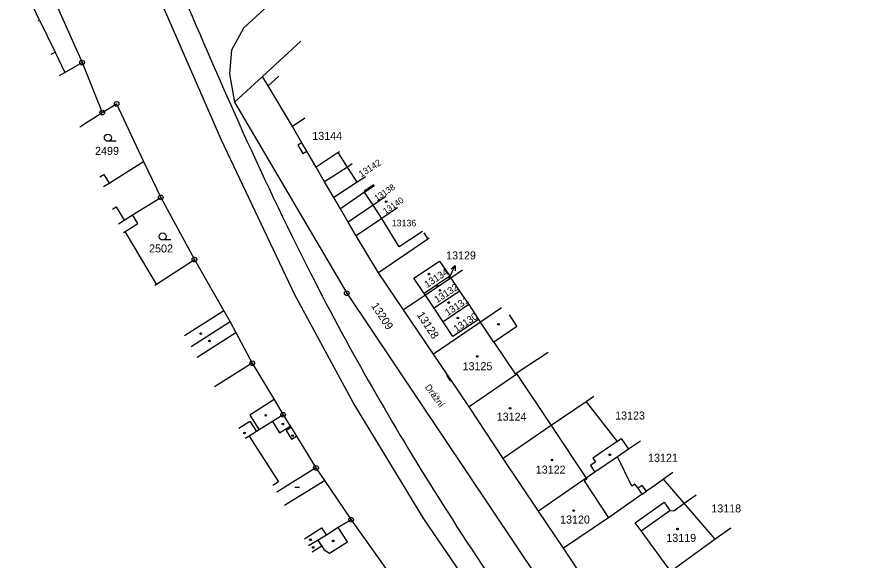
# Model space of a CAD drawing. Extents: x -825057 to -819383, y -1071633 to -1067888.
# Drawn here: x -820683.2 to -820503, y -1071267 to -1071151.6 of the extents above; entities that cross this region are included whole.
import ezdxf

# ---------------------------------------------------------------- set-up
doc = ezdxf.new("R2010")
doc.units = 0
for name, color, linetype in [('Vrstva 1', 7, 'Continuous'), ('Vrstva 10', 7, 'Continuous'), ('Vrstva 15', 7, 'Continuous'), ('Vrstva 16', 7, 'Continuous'), ('Vrstva 18', 7, 'Continuous'), ('Vrstva 19', 7, 'Continuous'), ('Vrstva 24', 7, 'Continuous'), ('Vrstva 25', 7, 'Continuous'), ('Vrstva 4', 7, 'Continuous')]:
    doc.layers.add(name, color=color, linetype=linetype)

msp = doc.modelspace()

# ---------------------------------------------------------------- linework, layer by layer
at = {"layer": 'Vrstva 1'}
for p, q in [((-820603.93, -1071125.41), (-820635.05, -1071153.94)), ((-820683.15, -1071130.16), (-820669.33, -1071161.28)), ((-820678.34, -1071152.24), (-820679.65, -1071149.54)), ((-820678.67, -1071152.4), (-820678.34, -1071152.24)), ((-820678.34, -1071152.24), (-820675.07, -1071159.07)), ((-820635.05, -1071153.94), (-820637.57, -1071158.64)), ((-820630.96, -1071164.21), (-820622.83, -1071156.74)), ((-820675.07, -1071159.07), (-820672.99, -1071163.41)), ((-820637.57, -1071158.64), (-820637.97, -1071163.66)), ((-820672.99, -1071163.41), (-820669.33, -1071161.28)), ((-820669.33, -1071161.28), (-820665.05, -1071171.9)), ((-820674.08, -1071164.01), (-820672.99, -1071163.41)), ((-820637.97, -1071163.66), (-820636.96, -1071169.72)), ((-820636.96, -1071169.72), (-820630.96, -1071164.21)), ((-820629.77, -1071166.21), (-820630.96, -1071164.21)), ((-820624.6, -1071174.87), (-820629.77, -1071166.21)), ((-820665.05, -1071171.9), (-820662, -1071170.07)), ((-820662, -1071170.07), (-820656.29, -1071182.27)), ((-820636.96, -1071169.72), (-820613.1, -1071210.27)), ((-820669.77, -1071174.94), (-820665.05, -1071171.9)), ((-820622.03, -1071173.12), (-820624.6, -1071174.87)), ((-820622.62, -1071178.29), (-820624.6, -1071174.87)), ((-820621.57, -1071180.1), (-820622.62, -1071178.29)), ((-820619.61, -1071183.48), (-820621.57, -1071180.1)), ((-820614.93, -1071180.4), (-820619.61, -1071183.48)), ((-820614.65, -1071180.22), (-820614.93, -1071180.4)), ((-820663.57, -1071186.87), (-820656.29, -1071182.27)), ((-820656.29, -1071182.27), (-820652.59, -1071189.92)), ((-820617.79, -1071186.59), (-820619.61, -1071183.48)), ((-820612.95, -1071183.46), (-820617.79, -1071186.59)), ((-820611.95, -1071182.81), (-820612.95, -1071183.46)), ((-820665.57, -1071185.57), (-820664.7, -1071185.02)), ((-820664.7, -1071185.02), (-820663.57, -1071186.87)), ((-820664.77, -1071187.62), (-820663.57, -1071186.87)), ((-820615.84, -1071189.94), (-820617.79, -1071186.59)), ((-820610.85, -1071186.71), (-820615.84, -1071189.94)), ((-820609.08, -1071185.57), (-820610.85, -1071186.71)), ((-820609.3, -1071188.77), (-820614.45, -1071192.34)), ((-820607.35, -1071187.24), (-820609.41, -1071188.59)), ((-820609.41, -1071188.59), (-820609.3, -1071188.77)), ((-820609.3, -1071188.77), (-820607.22, -1071187.37)), ((-820658.59, -1071193.65), (-820652.59, -1071189.92)), ((-820652.59, -1071189.92), (-820645.44, -1071203.12)), ((-820614.45, -1071192.34), (-820615.84, -1071189.94)), ((-820604.77, -1071189.72), (-820607.49, -1071191.58)), ((-820612.78, -1071195.19), (-820614.45, -1071192.34)), ((-820607.49, -1071191.58), (-820612.78, -1071195.19)), ((-820602.3, -1071192.1), (-820605.67, -1071194.4)), ((-820660.36, -1071194.76), (-820658.59, -1071193.65)), ((-820657.47, -1071195.44), (-820658.59, -1071193.65)), ((-820605.67, -1071194.4), (-820611.07, -1071198.11)), ((-820661.59, -1071195.52), (-820660.36, -1071194.76)), ((-820660.2, -1071197.14), (-820657.47, -1071195.44)), ((-820611.07, -1071198.11), (-820612.78, -1071195.19)), ((-820653.54, -1071208.36), (-820660.2, -1071197.14)), ((-820596.71, -1071197.47), (-820595.88, -1071198.8)), ((-820606.35, -1071205.94), (-820611.07, -1071198.11)), ((-820595.88, -1071198.8), (-820606.35, -1071205.94)), ((-820595.56, -1071198.58), (-820595.88, -1071198.8)), ((-820653.54, -1071208.36), (-820645.44, -1071203.12)), ((-820645.44, -1071203.12), (-820639.21, -1071214.01)), ((-820598.82, -1071207.1), (-820593.37, -1071203.46)), ((-820593.37, -1071203.46), (-820591.23, -1071206.67)), ((-820601.01, -1071213.82), (-820606.35, -1071205.94)), ((-820591.23, -1071206.67), (-820596.65, -1071210.34)), ((-820591.23, -1071206.67), (-820590.96, -1071207.06)), ((-820588.48, -1071205.39), (-820590.96, -1071207.06)), ((-820653.88, -1071208.58), (-820653.54, -1071208.36)), ((-820596.65, -1071210.34), (-820598.82, -1071207.1)), ((-820590.96, -1071207.06), (-820596.4, -1071210.72)), ((-820590.96, -1071207.06), (-820589.12, -1071209.82)), ((-820613.1, -1071210.27), (-820567.96, -1071277.63)), ((-820596.4, -1071210.72), (-820596.65, -1071210.34)), ((-820589.12, -1071209.82), (-820594.55, -1071213.48)), ((-820589.12, -1071209.82), (-820587.2, -1071212.7)), ((-820596.4, -1071210.72), (-820601.01, -1071213.82)), ((-820594.55, -1071213.48), (-820596.4, -1071210.72)), ((-820639.21, -1071214.01), (-820637.88, -1071216.32)), ((-820594.66, -1071223.23), (-820601.01, -1071213.82)), ((-820592.63, -1071216.35), (-820594.55, -1071213.48)), ((-820587.2, -1071212.7), (-820592.63, -1071216.35)), ((-820587.2, -1071212.7), (-820585.1, -1071215.83)), ((-820580.21, -1071213.35), (-820584.7, -1071216.43)), ((-820585.1, -1071215.83), (-820590.53, -1071219.49)), ((-820585.1, -1071215.83), (-820584.7, -1071216.43)), ((-820637.88, -1071216.32), (-820646.15, -1071221.68)), ((-820637.88, -1071216.32), (-820636.66, -1071218.6)), ((-820584.7, -1071216.43), (-820594.66, -1071223.23)), ((-820590.53, -1071219.49), (-820592.63, -1071216.35)), ((-820636.66, -1071218.6), (-820633.16, -1071225.15)), ((-820591.73, -1071227.59), (-820594.66, -1071223.23)), ((-820570.32, -1071222.86), (-820577.08, -1071227.33)), ((-820633.16, -1071225.15), (-820641.16, -1071230.15)), ((-820633.16, -1071225.15), (-820628.53, -1071232.88)), ((-820590.95, -1071228.74), (-820591.73, -1071227.59)), ((-820577.21, -1071227.63), (-820587.11, -1071234.42)), ((-820576.97, -1071227.46), (-820577.21, -1071227.63)), ((-820577.08, -1071227.33), (-820576.97, -1071227.46)), ((-820587.11, -1071234.42), (-820590.95, -1071228.74)), ((-820560.58, -1071232.23), (-820562.23, -1071233.35)), ((-820628.53, -1071232.88), (-820626.61, -1071236.09)), ((-820562.23, -1071233.35), (-820569.68, -1071238.4)), ((-820562.23, -1071233.35), (-820555.68, -1071241.74)), ((-820579.87, -1071245.35), (-820587.11, -1071234.42)), ((-820628.85, -1071237.5), (-820631.69, -1071239.28)), ((-820626.61, -1071236.09), (-820628.85, -1071237.5)), ((-820626.61, -1071236.09), (-820625.11, -1071238.51)), ((-820631.69, -1071239.28), (-820632.28, -1071239.66)), ((-820625.11, -1071238.51), (-820624.92, -1071238.81)), ((-820624.92, -1071238.81), (-820623.79, -1071240.65)), ((-820569.68, -1071238.4), (-820579.87, -1071245.35)), ((-820633.8, -1071240.61), (-820634.66, -1071241.15)), ((-820632.28, -1071239.66), (-820633.8, -1071240.61)), ((-820623.79, -1071240.65), (-820619.63, -1071247.37)), ((-820555.68, -1071241.74), (-820554.83, -1071241.14)), ((-820554.83, -1071241.14), (-820553.23, -1071243.42)), ((-820550.73, -1071241.71), (-820553.23, -1071243.42)), ((-820553.23, -1071243.42), (-820555.62, -1071245.05)), ((-820572.35, -1071256.57), (-820579.87, -1071245.35)), ((-820555.62, -1071245.05), (-820560.4, -1071248.31)), ((-820552.52, -1071251.26), (-820555.62, -1071245.05)), ((-820619.63, -1071247.37), (-820627.93, -1071252.57)), ((-820619.63, -1071247.37), (-820617.84, -1071250.03)), ((-820560.4, -1071248.31), (-820562.23, -1071249.55)), ((-820543.8, -1071248.38), (-820545.8, -1071249.8)), ((-820617.84, -1071250.03), (-820612.18, -1071258.39)), ((-820562.23, -1071249.55), (-820572.35, -1071256.57)), ((-820545.8, -1071249.8), (-820547.69, -1071251.1)), ((-820541.44, -1071254.9), (-820545.8, -1071249.8)), ((-820551.87, -1071250.81), (-820552.52, -1071251.26)), ((-820551.22, -1071251.72), (-820551.87, -1071250.81)), ((-820550.32, -1071251.09), (-820551.22, -1071251.72)), ((-820549.44, -1071252.34), (-820550.32, -1071251.09)), ((-820547.69, -1071251.1), (-820549.44, -1071252.34)), ((-820550.34, -1071252.97), (-820557.48, -1071258)), ((-820550.34, -1071252.97), (-820549.44, -1071252.34)), ((-820534.83, -1071262.53), (-820541.44, -1071254.9)), ((-820567.06, -1071264.43), (-820572.35, -1071256.57)), ((-820612.18, -1071258.39), (-820614.9, -1071260.07)), ((-820612.18, -1071258.39), (-820604.65, -1071268.97)), ((-820557.48, -1071258), (-820567.06, -1071264.43)), ((-820614.9, -1071260.07), (-820617.43, -1071261.64)), ((-820531.54, -1071260.17), (-820534.83, -1071262.53)), ((-820619.15, -1071262.7), (-820621.2, -1071263.97)), ((-820617.43, -1071261.64), (-820619.15, -1071262.7)), ((-820534.83, -1071262.53), (-820544.28, -1071269.4)), ((-820558.89, -1071276.65), (-820567.06, -1071264.43))]:
    msp.add_line(p, q, dxfattribs=at)
at = {"layer": 'Vrstva 10'}
for p, q in [((-820639.69, -1071177.76), (-820652.58, -1071148.22)), ((-820624.12, -1071210.63), (-820639.69, -1071177.76)), ((-820611.74, -1071233.47), (-820624.12, -1071210.63)), ((-820596.75, -1071258.19), (-820611.74, -1071233.47)), ((-820561.35, -1071309.57), (-820596.75, -1071258.19))]:
    msp.add_line(p, q, dxfattribs=at)
msp.add_spline([(-820648.37, -1071145.75), (-820635.21, -1071175.92), (-820619.77, -1071208), (-820606.88, -1071231.72), (-820592.84, -1071254.92), (-820557.31, -1071306.48), (-820522.72, -1071349.67), (-820487.72, -1071388.36), (-820440.04, -1071434.15), (-820382.01, -1071481.32), (-820258.78, -1071573.12)], degree=3, dxfattribs=at)
at = {"layer": 'Vrstva 16'}
msp.add_line((-820591.35, -1071207.09), (-820590.052, -1071204.385), dxfattribs=at)
msp.add_lwpolyline([(-820590.935, -1071205.071), (-820590.052, -1071204.385), (-820590.034, -1071205.503)], dxfattribs=at)
at = {"layer": 'Vrstva 24'}
for centre, radius in [((-820669.33, -1071161.28), 0.5), ((-820669.33, -1071161.28), 0.0327), ((-820662, -1071170.07), 0.5), ((-820662, -1071170.07), 0.0327), ((-820665.05, -1071171.9), 0.5), ((-820665.05, -1071171.9), 0.0327), ((-820652.59, -1071189.92), 0.5), ((-820652.59, -1071189.92), 0.0327), ((-820645.44, -1071203.12), 0.5), ((-820645.44, -1071203.12), 0.0327), ((-820613.1, -1071210.27), 0.5), ((-820613.1, -1071210.27), 0.0327), ((-820633.16, -1071225.15), 0.5), ((-820633.16, -1071225.15), 0.0327), ((-820626.61, -1071236.09), 0.5), ((-820626.61, -1071236.09), 0.0327), ((-820619.63, -1071247.37), 0.5), ((-820619.63, -1071247.37), 0.0327), ((-820612.18, -1071258.39), 0.5), ((-820612.18, -1071258.39), 0.0327)]:
    msp.add_circle(centre, radius, dxfattribs=at)
at = {"layer": 'Vrstva 25'}
for p, q in [((-820662.08, -1071178), (-820663.83, -1071178)), ((-820650.45, -1071198.96), (-820652.2, -1071198.96)), ((-820624.12, -1071251.47), (-820623.12, -1071251.47))]:
    msp.add_line(p, q, dxfattribs=at)
for centre, radius in [((-820663.83, -1071177.25), 0.75), ((-820604.72, -1071190.82), 0.175), ((-820652.2, -1071198.21), 0.75), ((-820595.63, -1071206.21), 0.175), ((-820593.82, -1071208.75), 0.175), ((-820593.28, -1071209.67), 0.175), ((-820591.44, -1071212.26), 0.175), ((-820589.5, -1071215.53), 0.175), ((-820580.87, -1071216.89), 0.175), ((-820644.14, -1071218.84), 0.175), ((-820642.26, -1071220.41), 0.175), ((-820585.36, -1071223.7), 0.175), ((-820578.4, -1071234.73), 0.175), ((-820630.33, -1071236.21), 0.175), ((-820626.67, -1071238.05), 0.175), ((-820634.81, -1071239.95), 0.175), ((-820624.61, -1071240.54), 0.175), ((-820557.22, -1071244.6), 0.175), ((-820569.5, -1071245.72), 0.175), ((-820564.91, -1071256.46), 0.175), ((-820542.83, -1071260.39), 0.175), ((-820620.81, -1071262.65), 0.175), ((-820616, -1071262.88), 0.175), ((-820620.23, -1071264.28), 0.175)]:
    msp.add_circle(centre, radius, dxfattribs=at)
at = {"layer": 'Vrstva 4'}
for p, q in [((-820675.87, -1071159.49), (-820675.07, -1071159.07)), ((-820629.77, -1071166.21), (-820627.53, -1071164.16)), ((-820622.62, -1071178.29), (-820623.5, -1071178.79)), ((-820623.5, -1071178.79), (-820622.44, -1071180.61)), ((-820622.44, -1071180.61), (-820621.57, -1071180.1)), ((-820612.95, -1071183.46), (-820614.93, -1071180.4)), ((-820610.85, -1071186.71), (-820612.95, -1071183.46)), ((-820607.49, -1071191.58), (-820609.3, -1071188.77)), ((-820662.87, -1071192.42), (-820662.11, -1071191.95)), ((-820662.11, -1071191.95), (-820660.36, -1071194.76)), ((-820605.67, -1071194.4), (-820607.49, -1071191.58)), ((-820601.99, -1071200.45), (-820605.67, -1071194.4)), ((-820660.52, -1071197.34), (-820660.2, -1071197.14)), ((-820597.03, -1071197.17), (-820601.99, -1071200.45)), ((-820639.21, -1071214.01), (-820647.54, -1071219.33)), ((-820578.63, -1071214.86), (-820576.97, -1071217.31)), ((-820581.88, -1071220.64), (-820584.7, -1071216.43)), ((-820576.97, -1071217.31), (-820581.88, -1071220.64)), ((-820644.85, -1071223.88), (-820636.66, -1071218.6)), ((-820581.88, -1071220.64), (-820577.21, -1071227.63)), ((-820591.73, -1071227.59), (-820591.92, -1071227.71)), ((-820591.92, -1071227.71), (-820591.14, -1071228.87)), ((-820576.97, -1071227.46), (-820569.68, -1071238.4)), ((-820591.14, -1071228.87), (-820590.95, -1071228.74)), ((-820628.53, -1071232.88), (-820633.67, -1071236.2)), ((-820635.99, -1071238.91), (-820633.69, -1071237.44)), ((-820633.69, -1071237.44), (-820632.28, -1071239.66)), ((-820633.67, -1071236.2), (-820631.69, -1071239.28)), ((-820628.85, -1071237.5), (-820627.37, -1071239.95)), ((-820627.37, -1071239.95), (-820625.11, -1071238.51)), ((-820624.92, -1071238.81), (-820625.94, -1071239.44)), ((-820625.94, -1071239.44), (-820624.81, -1071241.28)), ((-820569.68, -1071238.4), (-820562.23, -1071249.55)), ((-820633.8, -1071240.61), (-820627.56, -1071250.34)), ((-820624.81, -1071241.28), (-820623.79, -1071240.65)), ((-820555.68, -1071241.74), (-820560.8, -1071245.32)), ((-820560.28, -1071246.06), (-820561.32, -1071246.87)), ((-820560.8, -1071245.32), (-820560.28, -1071246.06)), ((-820561.32, -1071246.87), (-820560.4, -1071248.31)), ((-820626.32, -1071255.28), (-820617.84, -1071250.03)), ((-820562.1, -1071249.74), (-820562.68, -1071250.14)), ((-820562.68, -1071250.14), (-820557.48, -1071258)), ((-820562.23, -1071249.55), (-820562.1, -1071249.74)), ((-820627.56, -1071250.34), (-820628.79, -1071251.1)), ((-820550.34, -1071252.97), (-820551.22, -1071251.72)), ((-820541.44, -1071254.9), (-820538.89, -1071253.1)), ((-820551.83, -1071259.02), (-820545.68, -1071254.67)), ((-820545.68, -1071254.67), (-820544.47, -1071256.44)), ((-820543.62, -1071256.51), (-820541.44, -1071254.9)), ((-820550.56, -1071260.76), (-820544.47, -1071256.44)), ((-820544.47, -1071256.44), (-820543.62, -1071256.51)), ((-820550.56, -1071260.76), (-820551.83, -1071259.02)), ((-820622.08, -1071262.48), (-820618.44, -1071260.1)), ((-820618.44, -1071260.1), (-820617.43, -1071261.64)), ((-820612.93, -1071263.11), (-820614.9, -1071260.07)), ((-820544.28, -1071269.4), (-820550.56, -1071260.76)), ((-820618.38, -1071263.94), (-820619.15, -1071262.7)), ((-820620.46, -1071265.23), (-820618.38, -1071263.94)), ((-820618.38, -1071263.94), (-820617.87, -1071264.76)), ((-820616.75, -1071265.5), (-820612.93, -1071263.11)), ((-820617.87, -1071264.76), (-820616.75, -1071265.5))]:
    msp.add_line(p, q, dxfattribs=at)

# ---------------------------------------------------------------- texts
at = {"layer": 'Vrstva 15'}
msp.add_text('Drážní', height=1.4, rotation=306, dxfattribs=at).set_placement((-820596.565, -1071230.234))
at = {"layer": 'Vrstva 16'}
msp.add_text('13129', height=1.7, dxfattribs=at).set_placement((-820591.988, -1071203.09))
at = {"layer": 'Vrstva 18'}
for s, p in [('2499', (-820666.547, -1071180.88)), ('2502', (-820655.077, -1071201.61)), ('13123', (-820556.085, -1071237.1)), ('13121', (-820549.091, -1071246.09))]:
    msp.add_text(s, height=1.7, dxfattribs=at).set_placement(p)
msp.add_text('13209', height=1.7, rotation=303.3, dxfattribs=at).set_placement((-820607.977, -1071212.941))
at = {"layer": 'Vrstva 19'}
for s, height, p in [('13144', 1.7, (-820620.413, -1071177.7)), ('13136', 1.4, (-820603.538, -1071196.07)), ('13125', 1.7, (-820588.49, -1071226.63)), ('13124', 1.7, (-820581.238, -1071237.35)), ('13122', 1.7, (-820572.943, -1071248.59)), ('13118', 1.7, (-820535.654, -1071256.84)), ('13120', 1.7, (-820567.772, -1071259.2)), ('13119', 1.7, (-820545.206, -1071263.09))]:
    msp.add_text(s, height=height, dxfattribs=at).set_placement(p)
for s, height, rotation, p in [('13142', 1.4, 32.4, (-820610.02, -1071185.703)), ('13138', 1.3, 34.2, (-820606.692, -1071190.761)), ('13140', 1.3, 34.2, (-820604.856, -1071193.536)), ('13134', 1.5, 33.3, (-820596.021, -1071209.193)), ('13129', 0.2, 33.3, (-820591.542, -1071207.216)), ('13132', 1.5, 33.3, (-820593.909, -1071212.428)), ('13131', 1.5, 33.3, (-820591.651, -1071215.175)), ('13128', 1.7, 303.3, (-820598.285, -1071214.882)), ('13130', 1.5, 33.3, (-820589.794, -1071218.612))]:
    msp.add_text(s, height=height, rotation=rotation, dxfattribs=at).set_placement(p)

doc.saveas('drawing.dxf')
